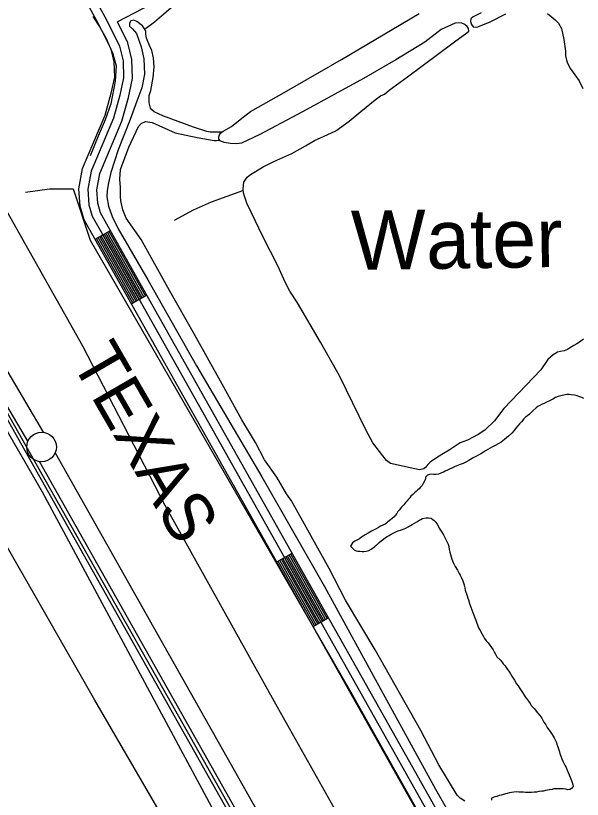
# Model space of a CAD drawing. Extents: x 3177185 to 3215018, y 812988 to 838321.
# Drawn here: x 3192464 to 3193420, y 824566 to 825889 of the extents above; entities that cross this region are included whole.
import ezdxf

# ---------------------------------------------------------------- set-up
doc = ezdxf.new("R2010")
doc.units = 0
for name, color, linetype in [('V-LEVE-TOET', 7, 'Continuous'), ('V-RAIL-IDEN', 7, 'Continuous'), ('V-RAIL-TRAK', 7, 'Continuous'), ('V-RIVR-IDEN', 7, 'Continuous'), ('V-ROAD-CNTR', 7, 'Continuous'), ('V-SURV-LINE', 7, 'Continuous'), ('V-TOPO-SHOR', 7, 'Continuous')]:
    doc.layers.add(name, color=color, linetype=linetype)

msp = doc.modelspace()

# ---------------------------------------------------------------- linework, layer by layer
at = {"layer": 'V-LEVE-TOET'}
for points in [[(3192444, 825569.1), (3192576.8, 825332.2), (3192715.7, 825063.1), (3192905.6, 824722.8), (3193107.9, 824362.3), (3193312.3, 824000.4), (3193506.6, 823644.9), (3193758.4, 823202.4)], [(3193584.3, 822982.9), (3193407.8, 823299.3), (3193245.4, 823590.8), (3193227.2, 823623), (3193224.5, 823626.5), (3193223, 823629.3), (3193219.8, 823632.7), (3193193.4, 823677.9), (3193057.2, 823923.2), (3192861.4, 824271.3), (3192736.1, 824495.3), (3192734.4, 824499), (3192733.6, 824501.5), (3192730.5, 824505.5), (3192598.1, 824733.8), (3192434.2, 825019.2)]]:
    msp.add_lwpolyline(points, dxfattribs=at)
at = {"layer": 'V-RAIL-TRAK'}
msp.add_lwpolyline([(3193727.3, 822943), (3193577.7, 823206), (3193415.9, 823494.6), (3193219.9, 823842.7), (3193027.5, 824182.9), (3192797.1, 824592.3), (3192558.2, 825016.7), (3192352.2, 825381.7), (3192184.3, 825679.9), (3191974.4, 826050.6), (3191871.7, 826233.9)], dxfattribs=at)
at = {"layer": 'V-ROAD-CNTR'}
for p, q in [((3192598.3, 825511.9), (3192624.4, 825526.6)), ((3192659.6, 825402.9), (3192685.7, 825417.6)), ((3192904.7, 824967.2), (3192930.9, 824981.9)), ((3192966, 824858.2), (3192992.2, 824872.9))]:
    msp.add_line(p, q, dxfattribs=at)
for points in [[(3193916.6, 823184.2), (3193721.8, 823525.6), (3193306.3, 824253.5), (3192602.8, 825503.8), (3192579.7, 825544.8), (3192573, 825567.5), (3192571, 825597.1), (3192577.3, 825631.2), (3192615.1, 825721.3), (3192625.4, 825758.7), (3192631.4, 825785.7), (3192630.5, 825811.3), (3192625.4, 825832.9), (3192604.1, 825875.3), (3192381.8, 826278.2), (3192358.9, 826315.5), (3192335.4, 826340.9), (3192319.5, 826354.7), (3192289.4, 826371.6), (3192167.7, 826420.9)], [(3193020.8, 826331.5), (3193004.6, 826293.2), (3192959.1, 826207.6), (3192913.9, 826125.6), (3192880.4, 826080.8), (3192844.1, 826039.9), (3192788.9, 825983.5), (3192730.3, 825933.7), (3192692.5, 825908.3), (3192635.9, 825878.9)], [(3192394.8, 826285.7), (3192617.4, 825882.3), (3192639.6, 825838), (3192645.5, 825813.3), (3192646.5, 825784.4), (3192640, 825755), (3192629.3, 825716.4), (3192591.7, 825626.9), (3192586.1, 825596.3), (3192587.9, 825570.2), (3192593.6, 825550.7), (3192615.9, 825511.2), (3193319.3, 824260.9), (3193734.8, 823533), (3193929.6, 823191.6)], [(3191892.3, 826207.1), (3193654.2, 823085.5)], [(3193712.7, 823602), (3193332.4, 824268.3), (3192629, 825518.5), (3192607.5, 825556.6), (3192602.7, 825572.9), (3192601.2, 825595.4), (3192606.2, 825622.6), (3192643.5, 825711.5), (3192654.5, 825751.4), (3192661.6, 825783), (3192660.4, 825815.3), (3192653.8, 825843.2), (3192635.9, 825878.9)], [(3192670, 825408.8), (3192613.3, 825509.7), (3192608.7, 825517.7)], [(3192672.6, 825410.3), (3192615.9, 825511.2), (3192611.3, 825519.2)], [(3192675.3, 825411.7), (3192618.5, 825512.6), (3192614, 825520.7)], [(3192677.9, 825413.2), (3192621.1, 825514.1), (3192616.6, 825522.2)], [(3192680.5, 825414.7), (3192623.7, 825515.6), (3192619.2, 825523.6)], [(3192683.1, 825416.2), (3192626.3, 825517), (3192621.8, 825525.1)], [(3192662.2, 825404.4), (3192605.4, 825505.3), (3192600.9, 825513.3)], [(3192664.8, 825405.9), (3192608, 825506.7), (3192603.5, 825514.8)], [(3192667.4, 825407.3), (3192610.6, 825508.2), (3192606.1, 825516.3)], [(3192979.1, 824865.6), (3192917.8, 824974.5)], [(3192981.7, 824867), (3192920.4, 824976)], [(3192984.3, 824868.5), (3192923, 824977.5)], [(3192986.9, 824870), (3192925.7, 824978.9)], [(3192989.6, 824871.5), (3192928.3, 824980.4)], [(3192968.6, 824859.7), (3192907.4, 824968.6)], [(3192971.3, 824861.2), (3192910, 824970.1)], [(3192973.9, 824862.6), (3192912.6, 824971.6)], [(3192976.5, 824864.1), (3192915.2, 824973)]]:
    msp.add_lwpolyline(points, dxfattribs=at)
at = {"layer": 'V-SURV-LINE'}
for points in [[(3192016.4, 826025.5), (3192510.8, 825186.1)], [(3192484.9, 825170.8), (3191990.6, 826010.3)], [(3192530.9, 825151.2), (3193991.3, 822560.8)], [(3193965.1, 822546.1), (3192504.7, 825136.5)]]:
    msp.add_lwpolyline(points, dxfattribs=at)
msp.add_circle((3192508, 825161.2), 25, dxfattribs=at)
at = {"layer": 'V-TOPO-SHOR'}
for points in [[(3195564, 819660.7), (3195052.1, 820581.1), (3194839.3, 820937.7), (3194281, 821921.4), (3194057, 822347), (3193780.9, 822818.6), (3193257.4, 823744.7), (3192803, 824538.5), (3192509.7, 825084.9), (3192365.9, 825332.3), (3191974.7, 826039.8)], [(3192683.1, 825867.9), (3192698.6, 825878.8), (3192718.2, 825895.9), (3192742.2, 825917.1), (3192762.9, 825934.5), (3192788.7, 825955.1)], [(3192594.3, 825888), (3192606.5, 825870), (3192617, 825850.5), (3192628, 825824.7), (3192633.6, 825804.6), (3192632.4, 825778.5), (3192625, 825740.7), (3192615.4, 825713.5), (3192603.7, 825685.9), (3192590.2, 825652.6)], [(3192812.1, 825692.6), (3192814.4, 825694.5), (3192828.2, 825702.1), (3192845.6, 825716.5), (3192860.4, 825727.4), (3192917.2, 825759.7), (3193014.2, 825815.1), (3193145.1, 825892.7)], [(3193249.4, 825894.3), (3193235.9, 825887.5), (3193232, 825883.9), (3193231.7, 825879.2), (3193233.1, 825874.4), (3193236.4, 825870.6), (3193242.1, 825869.8), (3193263.7, 825878.4), (3193291.2, 825892.6)], [(3193361.4, 825893.1), (3193367.5, 825887.8), (3193374.4, 825882.4), (3193379.9, 825876.7), (3193385.1, 825867.4), (3193388.9, 825848.9), (3193391.8, 825829.5), (3193392, 825821.3), (3193393.4, 825814.1), (3193395, 825808.9), (3193400.2, 825799.3), (3193414.9, 825779.5), (3193421.1, 825766.4)], [(3192812.1, 825692.6), (3192792.6, 825692.8), (3192786.7, 825693.7), (3192764.1, 825701.3), (3192712.8, 825720.5), (3192698.1, 825727), (3192693.8, 825730.1), (3192691.7, 825733.3), (3192689.3, 825741.9), (3192689.7, 825754.6), (3192692.4, 825762.9), (3192696.5, 825784.7), (3192697.7, 825803), (3192696.6, 825818), (3192694, 825830.5), (3192690.1, 825838.8), (3192685.1, 825851.1), (3192683.8, 825858.3), (3192683.9, 825862.7), (3192683, 825865.3), (3192678, 825872.1), (3192668.9, 825879.4), (3192663.7, 825881.6), (3192658.7, 825880.8), (3192656.3, 825876.5), (3192656.1, 825871.7), (3192661.4, 825867.3), (3192667.9, 825859.3), (3192673.1, 825844.7), (3192675.8, 825836.5), (3192680.7, 825816.2), (3192681.4, 825790.4), (3192677.2, 825767.3), (3192668.5, 825744.9), (3192657.4, 825714.2), (3192637.3, 825662.8), (3192624.9, 825624.4), (3192620.8, 825606.9), (3192618.7, 825594.1), (3192618, 825583.7), (3192620.7, 825567.7), (3192627.2, 825550.2), (3192637.1, 825529.5), (3192687.5, 825443.3), (3192769.2, 825298), (3192879.7, 825110.7), (3192985.5, 824925.7), (3193083.6, 824745.7), (3193172.7, 824583.7), (3193284.9, 824386.8)], [(3192899.8, 825643), (3192930.2, 825656.4), (3192953, 825669.7), (3192968.4, 825678.4), (3192985, 825685.9), (3193004.5, 825695.1), (3193027, 825711.1), (3193046.7, 825727.8), (3193070.6, 825747.3), (3193080, 825753.9), (3193086.4, 825757), (3193094.5, 825763.8), (3193125.1, 825785.8), (3193204.8, 825845.3), (3193225.3, 825860.2), (3193228.6, 825863.2), (3193228.4, 825867.5), (3193226, 825870.8), (3193222.1, 825874.4), (3193215.8, 825877.2), (3193205.5, 825876.8), (3193182.3, 825866.2), (3193154.6, 825844.6), (3193105.6, 825815), (3193051.3, 825783.4), (3192948.2, 825726.7), (3192876, 825688.8), (3192845.1, 825674.3), (3192837.6, 825673.1), (3192826.7, 825673.6), (3192816, 825675.3), (3192809.2, 825677.9), (3192807.2, 825681.1), (3192807.2, 825684.6), (3192808.1, 825688), (3192810, 825691.1), (3192812.1, 825692.6)], [(3193222, 824563.6), (3193214.4, 824568.6), (3193209.4, 824573.5), (3193178.3, 824624.6), (3193148, 824682.5), (3193070.6, 824818.6), (3193020.8, 824902.9), (3192993.2, 824955.9), (3192929.4, 825070.4), (3192921.2, 825082), (3192904.7, 825110), (3192884.1, 825139.4), (3192869.1, 825169), (3192846.1, 825207.1), (3192812.9, 825267.4), (3192765.8, 825351.3), (3192723.8, 825425.2), (3192676, 825511.6), (3192650.6, 825547.7), (3192645.1, 825561.7), (3192641.6, 825576.5), (3192640.9, 825583.5), (3192641.3, 825599.5), (3192640, 825613.5), (3192641, 825629.8), (3192655.4, 825667.4), (3192671.4, 825702.3), (3192676.3, 825707.2), (3192683.6, 825710.4), (3192694.5, 825708.8), (3192733.4, 825691.5), (3192770.6, 825683.8), (3192799.4, 825678.4), (3192803.1, 825678.4), (3192808.4, 825679.1)], [(3193371, 825316.8), (3193361.9, 825308.8), (3193350.3, 825291.5), (3193288, 825226.3), (3193272, 825205.3), (3193255.9, 825189.8), (3193244.5, 825182.1), (3193226.5, 825172.6), (3193214.4, 825168.1), (3193203.9, 825161.4), (3193195.7, 825155.9), (3193186, 825150.4), (3193178.6, 825145.9), (3193170.8, 825140.4), (3193163.4, 825135.7), (3193159.9, 825131.8), (3193156.3, 825126.9), (3193152.8, 825124.3), (3193145.8, 825122.5), (3193129.9, 825125.8), (3193096.7, 825133.5), (3193090.2, 825138.2), (3193083.6, 825146.1), (3193067.1, 825168.3), (3193054.9, 825190), (3193010.7, 825281.1), (3192978.5, 825338), (3192939.6, 825404.3), (3192926.7, 825424.5), (3192918.7, 825439.5), (3192907.2, 825465.7), (3192881.3, 825516.7), (3192861.4, 825557.6), (3192854.3, 825572.8), (3192850.3, 825584.7), (3192848.5, 825590.1), (3192848.2, 825596.1), (3192848.4, 825603.1), (3192849.2, 825608.3), (3192855, 825616.7), (3192860.2, 825621.4), (3192881.9, 825634.4), (3192890, 825637.9), (3192899.8, 825643)], [(3192480.9, 825591.1), (3192521.2, 825596.9), (3192561.4, 825596.9), (3192590.2, 825510.6), (3193027.4, 824751.3), (3193700.3, 823554.9), (3193890.2, 823215.5), (3194810.5, 821587.7), (3194919.8, 821386.4), (3195149.9, 820978), (3195149.9, 820885.9), (3195144.1, 820851.4), (3195103.9, 820788.1), (3195086.6, 820747.9)], [(3192732.1, 825544), (3192764.3, 825561.6), (3192794.6, 825575), (3192847.6, 825594.3)], [(3193422.3, 825343.5), (3193415.6, 825338.3), (3193411, 825335.4), (3193405.7, 825332.3), (3193398.7, 825328.1), (3193395.2, 825325.8), (3193389.6, 825323.4), (3193383.5, 825322.4), (3193378.3, 825321.3), (3193371, 825316.8)], [(3193422.7, 825243.1), (3193419.6, 825244.5), (3193414.6, 825246.5), (3193411.5, 825247.8), (3193407.3, 825248.8), (3193401.3, 825249.4), (3193397.9, 825249.6), (3193394.3, 825249.6), (3193391.2, 825249.1), (3193384.1, 825247.4), (3193379.7, 825246.4), (3193375, 825244.9), (3193370.4, 825242), (3193364.9, 825239.1), (3193360.1, 825236.9), (3193355.8, 825234.9), (3193352.8, 825233.6), (3193348.6, 825231.3), (3193345.5, 825229.6), (3193342.4, 825227.1), (3193337.4, 825222.6), (3193334, 825219.7), (3193330.9, 825216.4), (3193327.8, 825213.8), (3193324.2, 825211.6), (3193321.7, 825208.8), (3193317.8, 825203.8), (3193314.4, 825200.4), (3193311.7, 825197.1), (3193307.6, 825192.3), (3193305.3, 825189.2), (3193301.4, 825184.8)], [(3193301.4, 825184.8), (3193296, 825179.6), (3193292.3, 825176.5), (3193289.2, 825173.9), (3193286.3, 825171.5), (3193283.3, 825169.4), (3193279.3, 825167), (3193272.4, 825163.2), (3193268.7, 825161.5), (3193264.8, 825159.4), (3193256.8, 825154.7), (3193253.4, 825152.6), (3193249.3, 825149.8), (3193240.5, 825144.9), (3193237.1, 825143.2), (3193234.4, 825141.7), (3193231.4, 825140.1), (3193228.7, 825138.6), (3193223.5, 825135.7), (3193219.1, 825133.6), (3193214, 825131.5), (3193208.8, 825129.6), (3193204.4, 825127.6), (3193200.2, 825125.7), (3193196.2, 825123.7), (3193192.7, 825122.3), (3193188.8, 825120.5), (3193185.9, 825118.9), (3193182.5, 825117.4), (3193177.4, 825115.5), (3193173.9, 825114.5), (3193169.2, 825114.7), (3193165.9, 825115.3), (3193162.5, 825115), (3193159.1, 825113.9), (3193155.8, 825110.5), (3193155.5, 825107.4), (3193154.5, 825104.5), (3193151.9, 825099.5), (3193150, 825096.4), (3193147.3, 825093.3), (3193145.1, 825090.7), (3193142.6, 825088.7), (3193140.2, 825086.3), (3193137.4, 825083.7), (3193134.2, 825081), (3193131.1, 825078), (3193129.1, 825075.6), (3193126.5, 825072.5), (3193124.6, 825070.1), (3193122.3, 825067.8), (3193118.9, 825063.8), (3193115.3, 825059.6), (3193111.4, 825054.7), (3193109.2, 825052.1), (3193107.3, 825049), (3193104.7, 825045.4), (3193102.6, 825043.2), (3193099.3, 825040.4), (3193096.4, 825038.5), (3193092.2, 825034.9), (3193089.9, 825032.8), (3193087.4, 825030.8), (3193083.7, 825029.4), (3193079.6, 825027.3), (3193076.7, 825025.2), (3193072.5, 825022.9), (3193068.1, 825020.8), (3193064.5, 825019.2), (3193061.7, 825017.4), (3193059, 825015.6), (3193053.8, 825012.7), (3193050.8, 825010.9), (3193047.9, 825009), (3193044.2, 825006.4), (3193039.6, 825004.1), (3193036.4, 825002), (3193032.5, 824999.4), (3193030.8, 824996.7), (3193029.2, 824993.6), (3193033.1, 824989.7)], [(3193033.1, 824989.7), (3193035.2, 824987.4), (3193038.6, 824986.2), (3193041.7, 824985.4), (3193045.1, 824985.1), (3193048.7, 824984.6), (3193051.9, 824984.6), (3193055.5, 824985.4), (3193060.2, 824986.7), (3193064.1, 824988.6), (3193070, 824993.2), (3193072.7, 824995.6), (3193075.2, 824997.7), (3193077.5, 824999.8), (3193080.9, 825002.7), (3193084.6, 825005.8), (3193088, 825008.4), (3193091.1, 825010), (3193094.4, 825012), (3193098, 825013.9), (3193103.3, 825016.7), (3193106.7, 825018.5), (3193109.8, 825019.8), (3193115, 825021.4), (3193119.6, 825023.3), (3193122.7, 825024.4), (3193126.6, 825026.5), (3193130.3, 825028.6), (3193133.1, 825030.1), (3193137.2, 825032.5), (3193140.9, 825035), (3193144.6, 825037.1), (3193148.1, 825038.9), (3193150.8, 825040.3), (3193156.8, 825041.6), (3193160.9, 825041.8), (3193165.3, 825040.8), (3193168.2, 825039), (3193170.6, 825037.2), (3193173.4, 825034.3), (3193175.5, 825030.8), (3193177.4, 825027.1), (3193178.9, 825024.3), (3193181, 825020.6), (3193183.3, 825017.2), (3193186, 825012.8), (3193190.1, 825005), (3193191.7, 825001.7), (3193193.8, 824997.3), (3193194.8, 824993.4), (3193195.9, 824988.2), (3193197, 824983.4), (3193198.8, 824976), (3193200.1, 824972), (3193202.4, 824966), (3193204, 824962.9), (3193205.9, 824959.6), (3193209.5, 824953.4), (3193212.4, 824947.9), (3193214.2, 824944.6), (3193215.8, 824941.6), (3193218.7, 824935.4), (3193220.3, 824930), (3193221.5, 824926.3), (3193222.9, 824919.4), (3193225.8, 824910.2), (3193226.9, 824906.3), (3193228.2, 824903.2), (3193230.2, 824896.8), (3193232.3, 824890.8), (3193234.1, 824886.1), (3193235.7, 824881.7), (3193236.8, 824878.8), (3193239.2, 824872.8), (3193240.4, 824868.9), (3193241.5, 824865.6), (3193243.8, 824859.5), (3193245.4, 824856), (3193247.3, 824852.5), (3193251.4, 824845), (3193253.8, 824841.1), (3193255.2, 824838.1), (3193258.3, 824834.2), (3193261.2, 824830.8), (3193264.3, 824826.8), (3193266.9, 824823), (3193269.7, 824818.6), (3193271.6, 824815.2), (3193273.9, 824811.3), (3193276.2, 824807.2), (3193281.7, 824801.7), (3193284.3, 824798.6), (3193286.9, 824795.4), (3193289, 824792.9), (3193289.4, 824792.7), (3193292, 824789), (3193294.3, 824785.8), (3193296.1, 824782.8), (3193299, 824778.3), (3193301.4, 824774.4), (3193305.6, 824767.5)], [(3193305.6, 824767.5), (3193309.5, 824761.3), (3193311.8, 824758.1), (3193313.8, 824755.3), (3193316.2, 824751.9), (3193318.1, 824748.5), (3193320.6, 824744.9), (3193324, 824739.7), (3193325.9, 824736.8), (3193329.3, 824731.9), (3193332.1, 824728.2), (3193334.2, 824725.1), (3193338.9, 824720), (3193344.9, 824712.5), (3193348.6, 824708), (3193351.8, 824703.4), (3193355.6, 824696.9), (3193358.5, 824692.2), (3193361.2, 824687.8), (3193366.9, 824679.3), (3193369.2, 824676.1), (3193371.3, 824673.2), (3193372.7, 824670.4), (3193376.6, 824662.6), (3193377.4, 824659.7), (3193378.9, 824655.3), (3193381.5, 824646.7), (3193382.4, 824643.6), (3193384.1, 824639.5), (3193385.7, 824635), (3193387.6, 824630.7), (3193389.1, 824627.5), (3193391.5, 824622.8), (3193393, 824620), (3193394.9, 824615.8), (3193396.5, 824611.5), (3193398.1, 824607.6), (3193399.6, 824604.1), (3193400.7, 824601.1), (3193401.9, 824598), (3193404.1, 824591.7), (3193405.1, 824588), (3193402.1, 824584.6), (3193399.1, 824583.1), (3193395.8, 824582.6), (3193392.4, 824583.4), (3193387.7, 824584.3), (3193384.3, 824584.3), (3193383.9, 824584.3), (3193379.6, 824584.4), (3193376.5, 824584.3), (3193372.1, 824584), (3193370.5, 824583.5), (3193369.2, 824583.2), (3193365.1, 824582.7), (3193364.4, 824582.7), (3193361.7, 824582), (3193358.4, 824581.1), (3193356.6, 824580.6), (3193354.9, 824580.4), (3193351.8, 824580.1), (3193346.9, 824579.5), (3193343.2, 824578.8), (3193338.8, 824578.5), (3193334.7, 824578.2), (3193328.9, 824578.2), (3193324.6, 824578.2), (3193321.2, 824578.5), (3193317.3, 824578.4), (3193313.1, 824578.7), (3193309.4, 824578.9), (3193304.6, 824578.6), (3193300.9, 824578.1), (3193297.2, 824577.3), (3193293.6, 824576.5), (3193290.5, 824575.8), (3193287.1, 824574.7), (3193283.5, 824573.7), (3193279.8, 824572.8), (3193276.2, 824571.5), (3193272.8, 824570.7), (3193269.7, 824569.5), (3193266.9, 824568.2), (3193267.1, 824565)]]:
    msp.add_lwpolyline(points, dxfattribs=at)

# ---------------------------------------------------------------- texts
at = {"layer": 'V-RAIL-IDEN'}
msp.add_text('TEXAS', height=83, rotation=300.0114, dxfattribs=at).set_placement((3192556.3, 825306.6))
at = {"layer": 'V-RIVR-IDEN'}
msp.add_text('Water', height=100, rotation=0.8551, dxfattribs=at).set_placement((3193031, 825459.9))

doc.saveas('drawing.dxf')
